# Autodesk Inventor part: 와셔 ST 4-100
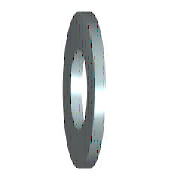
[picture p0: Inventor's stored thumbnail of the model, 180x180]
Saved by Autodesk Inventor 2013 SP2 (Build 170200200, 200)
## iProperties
IsCustomPart: 0
Created: 2012-02
Part Number: 와셔 ST 4-100
Material: 강철, 연강
Description: 평면 와셔 - 일반 시리즈 - 제품 등급 C
Document SubType Name: Modeling
Standard: ISO 7091
Designer: mduedu
Standard Revision: Second edition 2000-06-01
Standards Organization: ISO
Language: ko-KR
Size Designation: ST 4 - 100 HV
Categories: <MemberInstance><Categories><Category DisplayName="조임쇠" InternalName="e4da775c-781d-43d5-af7c-5136215cf5a6" Mnemonic="FSTN"><Category DisplayName="와셔" InternalN
Density: 7.86 g/cm^3
Mass: 0.492315 g
Surface Area: 1.70824 cm^2
Volume: 0.0626355 cm^3
Author: mduedu
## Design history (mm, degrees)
sketch "스케치"
  geometry: C1 r 5 at (0, 0); C2 r 2.25 at (0, 0); 1 further point
  constraints: 2 centre point, 2 coincident
  dimensions: "d0" = 4.5 diameter of C2 (= SD1); "d1" = 10 diameter of C1 (= SD2)
extrude "본체" new body sketch "스케치" distance "d2" = 1 (= SD); taper "d3" = 0 deg
workaxis "Work Axis1"
workplane "Work Plane1"
body "Solid1"
other parameters: "SD1" = 4.5 [user parameter; used in 1 equation term], "SD2" = 10 [user parameter; used in 1 equation term], "SD" = 1 [user parameter; used in 1 equation term], "d4" = 0, "d5" = 0, "d6" = 0, "d7" = 0, "NND" = 4 [user parameter]
